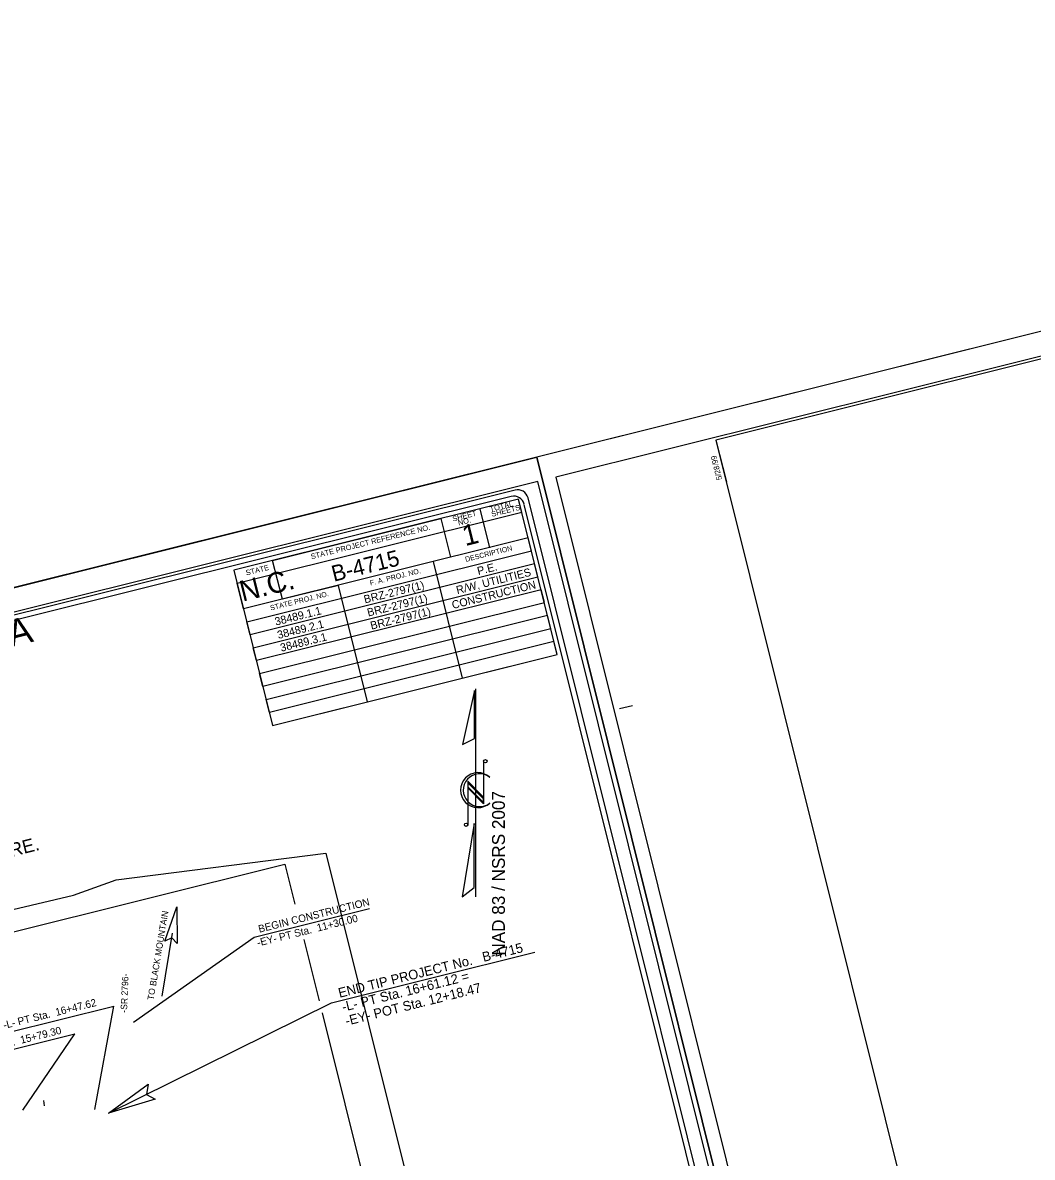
# Model space of a CAD drawing. Extents: x 1030323 to 1034123, y 654802 to 657751.
# Drawn here: x 1031475 to 1032422, y 656687 to 657751 of the extents above; entities that cross this region are included whole.
import ezdxf

# ---------------------------------------------------------------- set-up
doc = ezdxf.new("R2010")
doc.units = 0
for name, color, linetype in [('Old_Level_1', 7, 'Continuous'), ('Prop Horizontal Alignment Station Label', 7, 'Continuous'), ('Prop Horizontal Alignment Tick Small', 7, 'Continuous'), ('Prop Terminator CELL', 7, 'Continuous'), ('Sheet Clip Boundary CELL', 7, 'Continuous'), ('Sheet Cutting Line CELL', 7, 'Continuous'), ('Sheet Data Field CELL', 7, 'Continuous'), ('Sheet North Arrow CELL', 7, 'Continuous'), ('Sheet Plot Border Inside CELL', 7, 'Continuous'), ('Sheet Plot Border Outside CELL', 7, 'Continuous'), ('Sheet Summary CELL', 7, 'Continuous'), ('Sheet Title CELL', 7, 'Continuous')]:
    doc.layers.add(name, color=color, linetype=linetype)

msp = doc.modelspace()

# ---------------------------------------------------------------- linework, layer by layer
at = {"layer": 'Old_Level_1'}
msp.add_line((1031605.8, 656838.5), (1031615.7, 656897.5), dxfattribs=at)
at = {"layer": 'Prop Horizontal Alignment Station Label'}
for p, q in [((1031692.3, 656894), (1031800.4, 656920.9)), ((1031579.2, 656814.3), (1031692.3, 656894)), ((1031764.8, 656832.3), (1031955.3, 656879.9)), ((1031555.6, 656729), (1031764.8, 656832.3)), ((1031459.9, 656804.1), (1031560.6, 656829.2)), ((1031542.9, 656732.3), (1031560.6, 656829.2)), ((1031428.2, 656779.2), (1031523.9, 656803.1)), ((1031475.4, 656731.6), (1031523.9, 656803.1))]:
    msp.add_line(p, q, dxfattribs=at)
at = {"layer": 'Prop Horizontal Alignment Tick Small'}
msp.add_line((1031495.7, 656735.6), (1031495.1, 656740.6), dxfattribs=at)
at = {"layer": 'Prop Terminator CELL'}
for points in [[(1031608.5, 656890.1), (1031619.8, 656922.4), (1031620.1, 656887.9), (1031614.9, 656893.2)], [(1031599.4, 656742), (1031555.6, 656729), (1031592.7, 656756.2), (1031591.1, 656746.5)]]:
    msp.add_lwpolyline(points, close=True, dxfattribs=at)
at = {"layer": 'Sheet Clip Boundary CELL'}
msp.add_lwpolyline([(1031088.7, 656293.4), (1030994.1, 656269.6), (1030843.5, 656511.7), (1030969.2, 656567.2), (1030968.6, 656775.3), (1031272.6, 656874.3), (1031522.8, 656933.1), (1031562.8, 656947.6), (1031759.5, 656972.5), (1031879.7, 656490.6)], close=True, dxfattribs=at)
at = {"layer": 'Sheet Cutting Line CELL'}
for p, q in [((1033590.9, 657751.2), (1031957, 657343.8)), ((1030323, 656936.4), (1031957, 657343.8)), ((1031957, 657343.8), (1032223.1, 656276.4))]:
    msp.add_line(p, q, dxfattribs=at)
at = {"layer": 'Sheet North Arrow CELL'}
for p, q in [((1031899.9, 656931.7), (1031899.9, 657126.7)), ((1031907.3, 657058.9), (1031907.3, 657018.9)), ((1031912.8, 657044), (1031913, 657043.8)), ((1031907.3, 657025.1), (1031892.4, 657040)), ((1031892.4, 657040), (1031892.4, 656999.3)), ((1031907.3, 657023.6), (1031892.4, 657038.5)), ((1031892.4, 657038.5), (1031892.4, 657034.9)), ((1031907.3, 657020), (1031892.4, 657034.9)), ((1031892.4, 657034.9), (1031907.3, 657020)), ((1031907.3, 657018.9), (1031892.4, 657033.8)), ((1031907.3, 657020), (1031907.3, 657023.6))]:
    msp.add_line(p, q, dxfattribs=at)
for points in [[(1031898.6, 657125), (1031887.5, 657074.4), (1031898.6, 657080)], [(1031898.3, 657000.4), (1031887.3, 656931.7), (1031898.3, 656940.4)]]:
    msp.add_lwpolyline(points, close=True, dxfattribs=at)
for centre in [(1031908.9, 657058.8), (1031890.8, 656999.3)]:
    msp.add_circle(centre, 1.59, dxfattribs=at)
for centre, radius, start, end in [((1031902, 657031.7), 16.4, 47.84, 312.3941), ((1031903.6, 657031.7), 15.4, 53.095, 308.6287)]:
    msp.add_arc(centre, radius, start, end, dxfattribs=at)
at = {"layer": 'Sheet Plot Border Inside CELL'}
for points in [[(1033592, 657728.3), (1031975, 657325.1), (1032230.3, 656301.4), (1033847.3, 656704.5)], [(1030596.3, 655894), (1032213.3, 656297.1), (1031958, 657320.9), (1030341, 656917.7)]]:
    msp.add_lwpolyline(points, close=True, dxfattribs=at)
at = {"layer": 'Sheet Plot Border Outside CELL'}
for points in [[(1033590.9, 657751.2), (1031957, 657343.8), (1032223.1, 656276.4), (1033857.1, 656683.8)], [(1031957, 657343.8), (1030323, 656936.4), (1030589.1, 655869), (1032223.1, 656276.4)]]:
    msp.add_lwpolyline(points, close=True, dxfattribs=at)
at = {"layer": 'Sheet Summary CELL'}
for p, q in [((1032125.1, 657359.9), (1032134.8, 657320.7)), ((1032034.8, 657108.1), (1032046.9, 657111.1))]:
    msp.add_line(p, q, dxfattribs=at)
msp.add_lwpolyline([(1033580.5, 657722.8), (1032125.1, 657359.9), (1032379.1, 656341.1), (1033834.5, 656704)], close=True, dxfattribs=at)
at = {"layer": 'Sheet Title CELL'}
for points in [[(1031936.8, 657313), (1030500.8, 656954.9)], [(1031933.2, 657306.9), (1030555.4, 656963.4)], [(1031709.4, 657092.4), (1031976.2, 657158.9), (1031973.2, 657171.1), (1031706.4, 657104.5), (1031703.4, 657116.7), (1031970.2, 657183.2), (1031967.2, 657195.3), (1031700.4, 657128.8), (1031697.3, 657140.9), (1031964.2, 657207.5), (1031961.1, 657219.6), (1031694.3, 657153.1), (1031691.3, 657165.2), (1031958.1, 657231.7), (1031955.1, 657243.8), (1031688.3, 657177.3), (1031685.2, 657189.4), (1031952.1, 657256), (1031949, 657268.1), (1031682.2, 657201.6), (1031676.2, 657225.8), (1031943, 657292.4), (1031940, 657304.5), (1031673.1, 657237.9), (1031709.4, 657092.4), (1031798.3, 657114.6), (1031771.1, 657223.7), (1031718.6, 657210.6), (1031709.5, 657247), (1031867.2, 657286.3), (1031876.3, 657250), (1031860.1, 657245.9), (1031887.3, 657136.8), (1031976.2, 657158.9), (1031940, 657304.5), (1031903.6, 657295.4), (1031912.7, 657259)], [(1032147.3, 656489.4), (1031945.3, 657299.6)], [(1032198.1, 656306.3), (1031948.9, 657305.7)], [(1030948.5, 656691.2), (1030930.1, 656765.1), (1031721, 656962.3), (1031730.4, 656924.9)], [(1031738.7, 656891.6), (1031753, 656834.3)], [(1031755.8, 656823), (1031841.2, 656480.3), (1031050.3, 656283.1), (1030953.9, 656669.6)]]:
    msp.add_lwpolyline(points, dxfattribs=at)
for centre in [(1031939.2, 657303.3), (1031935.6, 657297.3)]:
    msp.add_arc(centre, 10, 14, 104, dxfattribs=at)

# ---------------------------------------------------------------- texts
at = {"layer": 'Old_Level_1'}
for s, rotation, p in [('TO BLACK MOUNTAIN', 80.4754, (1031597.9, 656834.5)), ('-SR 2796-', 87.5137, (1031572.9, 656823))]:
    msp.add_text(s, height=6, rotation=rotation, dxfattribs=at).set_placement(p)
at = {"layer": 'Prop Horizontal Alignment Station Label'}
for s, height, p in [('BEGIN CONSTRUCTION', 7, (1031697, 656898)), ('-EY- PT Sta.  11+30.00', 7, (1031695.8, 656885.1)), ('END TIP PROJECT No.   B-4715', 9, (1031772.3, 656837)), ('-L- PT Sta. 16+61.12 =', 9, (1031775.6, 656823.9)), ('-EY- POT Sta. 12+18.47', 9, (1031778.8, 656810.8)), ('-L- PT Sta.  16+47.62', 7, (1031457.8, 656807.8)), ('-L- PC Sta.  15+79.30', 7, (1031423.9, 656781.5))]:
    msp.add_text(s, height=height, rotation=14, dxfattribs=at).set_placement(p)
at = {"layer": 'Sheet Data Field CELL'}
for s, height, p in [('B-4715', 15, (1031766.8, 657227)), ('R/W, UTILITIES', 7.5, (1031882.6, 657215.4)), ('P.E.', 7.5, (1031902.3, 657233.3)), ('BRZ-2797(1)', 7.5, (1031796, 657206.7)), ('CONSTRUCTION', 7.5, (1031878.5, 657201.5)), ('BRZ-2797(1)', 7.5, (1031799.1, 657194.4)), ('38489.1.1', 7.5, (1031712.5, 657185.9)), ('BRZ-2797(1)', 7.5, (1031802.1, 657182.1)), ('38489.2.1', 7.5, (1031714.9, 657173.4)), ('38489.3.1 ', 7.5, (1031717.6, 657161.4))]:
    msp.add_text(s, height=height, rotation=14, dxfattribs=at).set_placement(p)
at = {"layer": 'Sheet North Arrow CELL'}
msp.add_text('        NAD 83 / NSRS 2007', height=12, rotation=90, dxfattribs=at).set_placement((1031927.2, 656840.9))
at = {"layer": 'Sheet Summary CELL'}
msp.add_text('5/28/99', height=5.25, rotation=104, dxfattribs=at).set_placement((1032130.9, 657323.1))
at = {"layer": 'Sheet Title CELL'}
for s, height, p in [('TOTAL', 5, (1031913.7, 657292.6)), ('SHEETS', 5, (1031915.2, 657287.9)), ('SHEET', 5, (1031878.7, 657283.5)), ('STATE PROJECT REFERENCE NO.', 5, (1031745.9, 657248.1)), ('NO.', 5, (1031883.9, 657279.7)), ('1', 19.3, (1031890, 657260.4)), ('DESCRIPTION', 4.8, (1031890.6, 657245.6)), ('N.C.', 19.35, (1031681.3, 657208.4)), ('STATE', 5, (1031684.9, 657232.9)), ('F. A. PROJ. NO.', 4.8, (1031801.2, 657223.4)), ('STATE PROJ. NO.', 4.8, (1031707.8, 657200.1)), ('STATE OF NORTH CAROLINA', 25, (1031028.4, 657057)), ('TYPE OF WORK: GRADING, DRAINAGE, PAVING, STRUCTURE.', 12.5, (1031005.1, 656854.5))]:
    msp.add_text(s, height=height, rotation=14, dxfattribs=at).set_placement(p)

doc.saveas('drawing.dxf')
